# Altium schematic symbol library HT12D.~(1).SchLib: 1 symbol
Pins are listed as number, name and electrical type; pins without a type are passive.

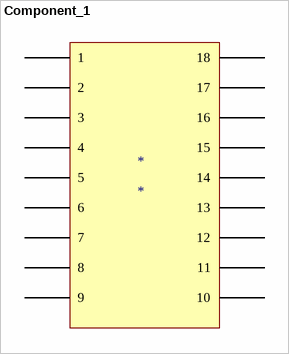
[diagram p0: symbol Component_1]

## Component_1
designator *
pins: 1, 2, 3, 4, 5, 6, 7, 8, 9, 10, 11, 12, 13, 14, 15, 16, 17, 18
